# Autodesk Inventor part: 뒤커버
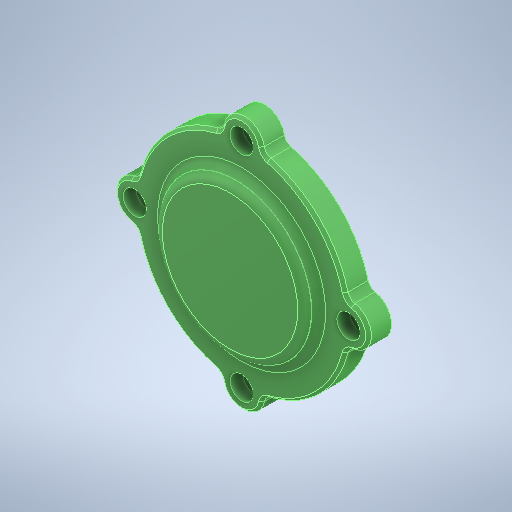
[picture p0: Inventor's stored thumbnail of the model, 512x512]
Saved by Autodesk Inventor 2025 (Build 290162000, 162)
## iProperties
Created: 2024-08
Part Number: 뒤커버
Material: 알루미늄 6061
Document SubType Name: Modeling
Designer: deana
Density: 2.71 g/cm^3
Appearance: 기본값
Company: 한국ATC센터
Author: jhkim
Sending System: Autodesk Inventor 2025
Preprocessor: ST-DEVELOPER v20
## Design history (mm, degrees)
feature "솔리드1"
node "솔리드2"
